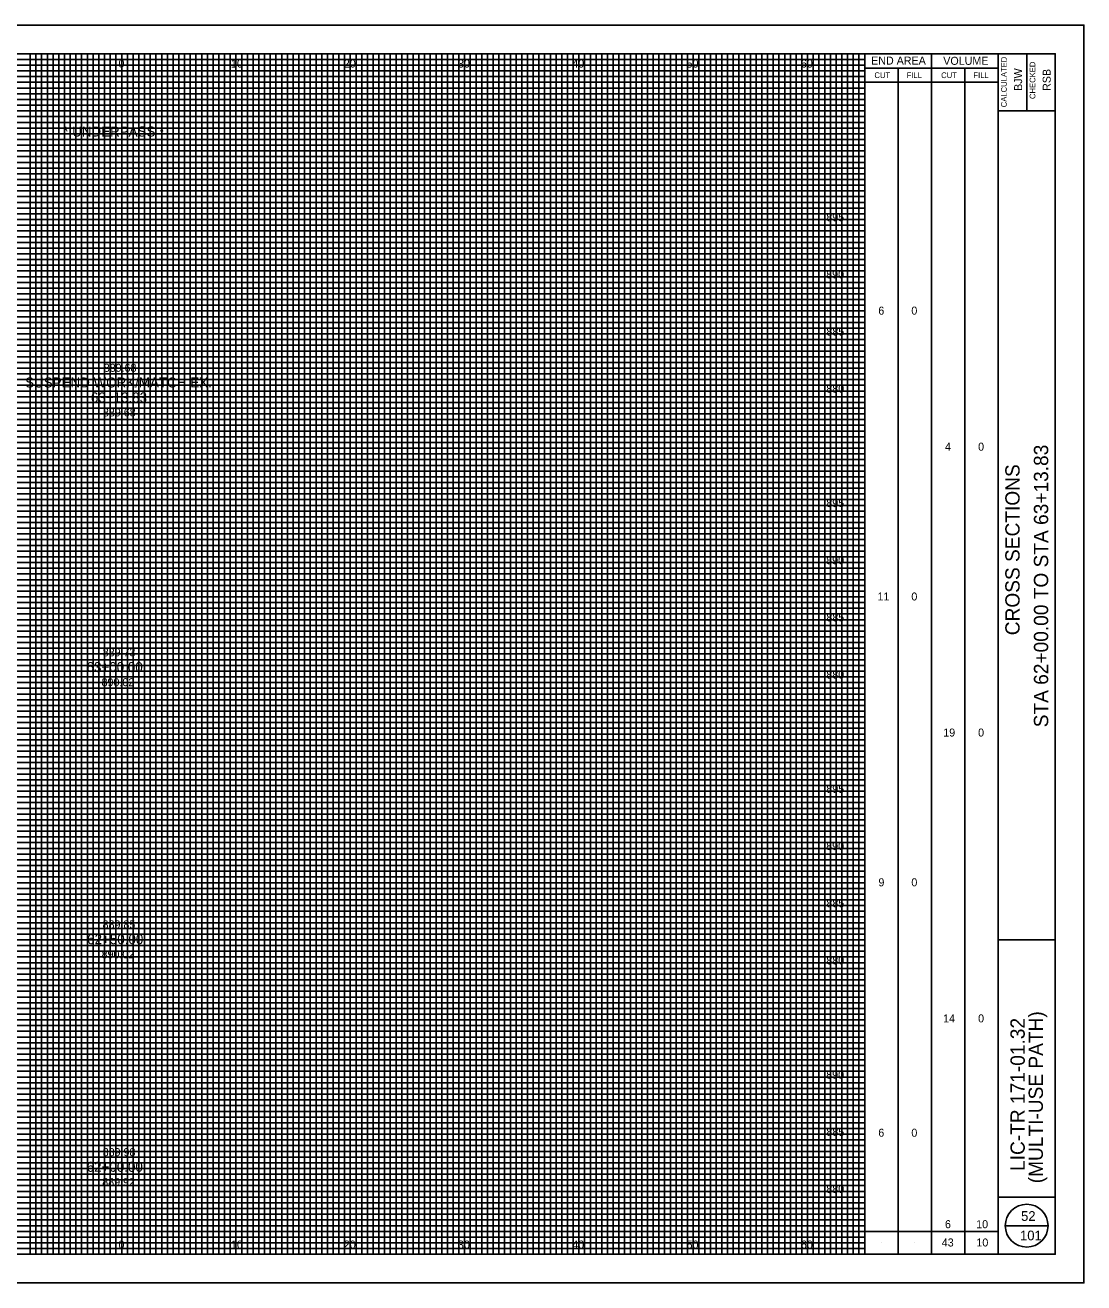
# Model space of a CAD drawing. Extents: x -10 to 160, y -2 to 222.
# Drawn here: x 67.4 to 160, y 112.5 to 222.5 of the extents above; entities that cross this region are included whole.
import ezdxf

# ---------------------------------------------------------------- set-up
doc = ezdxf.new("R2010")
doc.units = 0
for name, color, linetype in [('GK_Cells', 7, 'Continuous'), ('GK_Patterns', 7, 'Continuous'), ('SH_Cut_Line', 7, 'Continuous'), ('TX_P_10', 7, 'Continuous'), ('TX_X_10', 7, 'Continuous'), ('XS_P_Pavt_Surface', 7, 'Continuous'), ('XS_P_Text_Info', 7, 'Continuous'), ('XS_X_Ground_Line', 7, 'Continuous')]:
    doc.layers.add(name, color=color, linetype=linetype)

msp = doc.modelspace()

# ---------------------------------------------------------------- linework, layer by layer
at = {"layer": 'GK_Cells'}
msp.add_lwpolyline([(-10, 112.5), (160, 112.5), (160, 222.5), (-10, 222.5)], close=True, dxfattribs=at)
at = {"layer": 'TX_P_10'}
for p, q in [((140.83, 115), (140.83, 220)), ((146.67, 115), (146.67, 220)), ((140.83, 218.75), (152.5, 218.75)), ((143.75, 115), (143.75, 218.75)), ((149.58, 115), (149.58, 218.75)), ((140.83, 217.5), (152.5, 217.5)), ((140.83, 117), (152.5, 117)), ((153.12, 117.5), (156.88, 117.5)), ((142.29, 116), (142.29, 116)), ((145.21, 116), (145.21, 116)), ((148.12, 116), (148.12, 116)), ((151.04, 116), (151.04, 116))]:
    msp.add_line(p, q, dxfattribs=at)
msp.add_circle((155, 117.5), 1.87, dxfattribs=at)
at = {"layer": 'TX_X_10'}
for p, q in [((70.83, 115), (70.83, 220)), ((75.83, 115), (75.83, 220)), ((80.83, 115), (80.83, 220)), ((85.83, 115), (85.83, 220)), ((90.83, 115), (90.83, 220)), ((95.83, 115), (95.83, 220)), ((100.83, 115), (100.83, 220)), ((105.83, 115), (105.83, 220)), ((110.83, 115), (110.83, 220)), ((115.83, 115), (115.83, 220)), ((120.83, 115), (120.83, 220)), ((125.83, 115), (125.83, 220)), ((130.83, 115), (130.83, 220)), ((135.83, 115), (135.83, 220)), ((5.83, 215), (140.83, 215)), ((5.83, 210), (140.83, 210)), ((5.83, 205), (140.83, 205)), ((5.83, 200), (140.83, 200)), ((5.83, 195), (140.83, 195)), ((5.83, 190), (140.83, 190)), ((5.83, 185), (140.83, 185)), ((5.83, 180), (140.83, 180)), ((5.83, 175), (140.83, 175)), ((5.83, 170), (140.83, 170)), ((5.83, 165), (140.83, 165)), ((5.83, 160), (140.83, 160)), ((5.83, 155), (140.83, 155)), ((5.83, 150), (140.83, 150)), ((5.83, 145), (140.83, 145)), ((5.83, 140), (140.83, 140)), ((5.83, 135), (140.83, 135)), ((5.83, 130), (140.83, 130)), ((5.83, 125), (140.83, 125)), ((5.83, 120), (140.83, 120))]:
    msp.add_line(p, q, dxfattribs=at)
at = {"layer": 'XS_P_Pavt_Surface'}
for p, q in [((152.5, 115), (152.5, 220)), ((155, 220), (155, 215)), ((152.5, 215), (157.5, 215)), ((152.5, 142.5), (157.5, 142.5)), ((152.5, 120), (157.5, 120))]:
    msp.add_line(p, q, dxfattribs=at)
msp.add_lwpolyline([(0, 220), (157.5, 220), (157.5, 115), (0, 115)], close=True, dxfattribs=at)
at = {"layer": 'XS_X_Ground_Line'}
for p, q in [((5.83, 219.5), (140.83, 219.5)), ((5.83, 219), (140.83, 219)), ((67.83, 115), (67.83, 220)), ((68.33, 115), (68.33, 220)), ((68.83, 115), (68.83, 220)), ((69.33, 115), (69.33, 220)), ((69.83, 115), (69.83, 220)), ((70.33, 115), (70.33, 220)), ((71.33, 115), (71.33, 220)), ((71.83, 115), (71.83, 220)), ((72.33, 115), (72.33, 220)), ((72.83, 115), (72.83, 220)), ((73.33, 115), (73.33, 220)), ((73.83, 115), (73.83, 220)), ((74.33, 115), (74.33, 220)), ((74.83, 115), (74.83, 220)), ((75.33, 115), (75.33, 220)), ((76.33, 115), (76.33, 220)), ((76.83, 115), (76.83, 220)), ((77.33, 115), (77.33, 220)), ((77.83, 115), (77.83, 220)), ((78.33, 115), (78.33, 220)), ((78.83, 115), (78.83, 220)), ((79.33, 115), (79.33, 220)), ((79.83, 115), (79.83, 220)), ((80.33, 115), (80.33, 220)), ((81.33, 115), (81.33, 220)), ((81.83, 115), (81.83, 220)), ((82.33, 115), (82.33, 220)), ((82.83, 115), (82.83, 220)), ((83.33, 115), (83.33, 220)), ((83.83, 115), (83.83, 220)), ((84.33, 115), (84.33, 220)), ((84.83, 115), (84.83, 220)), ((85.33, 115), (85.33, 220)), ((86.33, 115), (86.33, 220)), ((86.83, 115), (86.83, 220)), ((87.33, 115), (87.33, 220)), ((87.83, 115), (87.83, 220)), ((88.33, 115), (88.33, 220)), ((88.83, 115), (88.83, 220)), ((89.33, 115), (89.33, 220)), ((89.83, 115), (89.83, 220)), ((90.33, 115), (90.33, 220)), ((91.33, 115), (91.33, 220)), ((91.83, 115), (91.83, 220)), ((92.33, 115), (92.33, 220)), ((92.83, 115), (92.83, 220)), ((93.33, 115), (93.33, 220)), ((93.83, 115), (93.83, 220)), ((94.33, 115), (94.33, 220)), ((94.83, 115), (94.83, 220)), ((95.33, 115), (95.33, 220)), ((96.33, 115), (96.33, 220)), ((96.83, 115), (96.83, 220)), ((97.33, 115), (97.33, 220)), ((97.83, 115), (97.83, 220)), ((98.33, 115), (98.33, 220)), ((98.83, 115), (98.83, 220)), ((99.33, 115), (99.33, 220)), ((99.83, 115), (99.83, 220)), ((100.33, 115), (100.33, 220)), ((101.33, 115), (101.33, 220)), ((101.83, 115), (101.83, 220)), ((102.33, 115), (102.33, 220)), ((102.83, 115), (102.83, 220)), ((103.33, 115), (103.33, 220)), ((103.83, 115), (103.83, 220)), ((104.33, 115), (104.33, 220)), ((104.83, 115), (104.83, 220)), ((105.33, 115), (105.33, 220)), ((106.33, 115), (106.33, 220)), ((106.83, 115), (106.83, 220)), ((107.33, 115), (107.33, 220)), ((107.83, 115), (107.83, 220)), ((108.33, 115), (108.33, 220)), ((108.83, 115), (108.83, 220)), ((109.33, 115), (109.33, 220)), ((109.83, 115), (109.83, 220)), ((110.33, 115), (110.33, 220)), ((111.33, 115), (111.33, 220)), ((111.83, 115), (111.83, 220)), ((112.33, 115), (112.33, 220)), ((112.83, 115), (112.83, 220)), ((113.33, 115), (113.33, 220)), ((113.83, 115), (113.83, 220)), ((114.33, 115), (114.33, 220)), ((114.83, 115), (114.83, 220)), ((115.33, 115), (115.33, 220)), ((116.33, 115), (116.33, 220)), ((116.83, 115), (116.83, 220)), ((117.33, 115), (117.33, 220)), ((117.83, 115), (117.83, 220)), ((118.33, 115), (118.33, 220)), ((118.83, 115), (118.83, 220)), ((119.33, 115), (119.33, 220)), ((119.83, 115), (119.83, 220)), ((120.33, 115), (120.33, 220)), ((121.33, 115), (121.33, 220)), ((121.83, 115), (121.83, 220)), ((122.33, 115), (122.33, 220)), ((122.83, 115), (122.83, 220)), ((123.33, 115), (123.33, 220)), ((123.83, 115), (123.83, 220)), ((124.33, 115), (124.33, 220)), ((124.83, 115), (124.83, 220)), ((125.33, 115), (125.33, 220)), ((126.33, 115), (126.33, 220)), ((126.83, 115), (126.83, 220)), ((127.33, 115), (127.33, 220)), ((127.83, 115), (127.83, 220)), ((128.33, 115), (128.33, 220)), ((128.83, 115), (128.83, 220)), ((129.33, 115), (129.33, 220)), ((129.83, 115), (129.83, 220)), ((130.33, 115), (130.33, 220)), ((131.33, 115), (131.33, 220)), ((131.83, 115), (131.83, 220)), ((132.33, 115), (132.33, 220)), ((132.83, 115), (132.83, 220)), ((133.33, 115), (133.33, 220)), ((133.83, 115), (133.83, 220)), ((134.33, 115), (134.33, 220)), ((134.83, 115), (134.83, 220)), ((135.33, 115), (135.33, 220)), ((136.33, 115), (136.33, 220)), ((136.83, 115), (136.83, 220)), ((137.33, 115), (137.33, 220)), ((137.83, 115), (137.83, 220)), ((138.33, 115), (138.33, 220)), ((138.83, 115), (138.83, 220)), ((139.33, 115), (139.33, 220)), ((139.83, 115), (139.83, 220)), ((140.33, 115), (140.33, 220)), ((5.83, 218.5), (140.83, 218.5)), ((5.83, 218), (140.83, 218)), ((5.83, 217.5), (140.83, 217.5)), ((5.83, 217), (140.83, 217)), ((5.83, 216.5), (140.83, 216.5)), ((5.83, 216), (140.83, 216)), ((5.83, 215.5), (140.83, 215.5)), ((5.83, 214.5), (140.83, 214.5)), ((5.83, 214), (140.83, 214)), ((5.83, 213.5), (140.83, 213.5)), ((5.83, 213), (140.83, 213)), ((5.83, 212.5), (140.83, 212.5)), ((5.83, 212), (140.83, 212)), ((5.83, 211.5), (140.83, 211.5)), ((5.83, 211), (140.83, 211)), ((5.83, 210.5), (140.83, 210.5)), ((5.83, 209.5), (140.83, 209.5)), ((5.83, 209), (140.83, 209)), ((5.83, 208.5), (140.83, 208.5)), ((5.83, 208), (140.83, 208)), ((5.83, 207.5), (140.83, 207.5)), ((5.83, 207), (140.83, 207)), ((5.83, 206.5), (140.83, 206.5)), ((5.83, 206), (140.83, 206)), ((5.83, 205.5), (140.83, 205.5)), ((5.83, 204.5), (140.83, 204.5)), ((5.83, 204), (140.83, 204)), ((5.83, 203.5), (140.83, 203.5)), ((5.83, 203), (140.83, 203)), ((5.83, 202.5), (140.83, 202.5)), ((5.83, 202), (140.83, 202)), ((5.83, 201.5), (140.83, 201.5)), ((5.83, 201), (140.83, 201)), ((5.83, 200.5), (140.83, 200.5)), ((5.83, 199.5), (140.83, 199.5)), ((5.83, 199), (140.83, 199)), ((5.83, 198.5), (140.83, 198.5)), ((5.83, 198), (140.83, 198)), ((5.83, 197.5), (140.83, 197.5)), ((5.83, 197), (140.83, 197)), ((5.83, 196.5), (140.83, 196.5)), ((5.83, 196), (140.83, 196)), ((5.83, 195.5), (140.83, 195.5)), ((5.83, 194.5), (140.83, 194.5)), ((5.83, 194), (140.83, 194)), ((5.83, 193.5), (140.83, 193.5)), ((5.83, 193), (140.83, 193)), ((5.83, 192.5), (140.83, 192.5)), ((5.83, 192), (140.83, 192)), ((5.83, 191.5), (140.83, 191.5)), ((5.83, 191), (140.83, 191)), ((5.83, 190.5), (140.83, 190.5)), ((5.83, 189.5), (140.83, 189.5)), ((5.83, 189), (140.83, 189)), ((5.83, 188.5), (140.83, 188.5)), ((5.83, 188), (140.83, 188)), ((5.83, 187.5), (140.83, 187.5)), ((5.83, 187), (140.83, 187)), ((5.83, 186.5), (140.83, 186.5)), ((5.83, 186), (140.83, 186)), ((5.83, 185.5), (140.83, 185.5)), ((5.83, 184.5), (140.83, 184.5)), ((5.83, 184), (140.83, 184)), ((5.83, 183.5), (140.83, 183.5)), ((5.83, 183), (140.83, 183)), ((5.83, 182.5), (140.83, 182.5)), ((5.83, 182), (140.83, 182)), ((5.83, 181.5), (140.83, 181.5)), ((5.83, 181), (140.83, 181)), ((5.83, 180.5), (140.83, 180.5)), ((5.83, 179.5), (140.83, 179.5)), ((5.83, 179), (140.83, 179)), ((5.83, 178.5), (140.83, 178.5)), ((5.83, 178), (140.83, 178)), ((5.83, 177.5), (140.83, 177.5)), ((5.83, 177), (140.83, 177)), ((5.83, 176.5), (140.83, 176.5)), ((5.83, 176), (140.83, 176)), ((5.83, 175.5), (140.83, 175.5)), ((5.83, 174.5), (140.83, 174.5)), ((5.83, 174), (140.83, 174)), ((5.83, 173.5), (140.83, 173.5)), ((5.83, 173), (140.83, 173)), ((5.83, 172.5), (140.83, 172.5)), ((5.83, 172), (140.83, 172)), ((5.83, 171.5), (140.83, 171.5)), ((5.83, 171), (140.83, 171)), ((5.83, 170.5), (140.83, 170.5)), ((5.83, 169.5), (140.83, 169.5)), ((5.83, 169), (140.83, 169)), ((5.83, 168.5), (140.83, 168.5)), ((5.83, 168), (140.83, 168)), ((5.83, 167.5), (140.83, 167.5)), ((5.83, 167), (140.83, 167)), ((5.83, 166.5), (140.83, 166.5)), ((5.83, 166), (140.83, 166)), ((5.83, 165.5), (140.83, 165.5)), ((5.83, 164.5), (140.83, 164.5)), ((5.83, 164), (140.83, 164)), ((5.83, 163.5), (140.83, 163.5)), ((5.83, 163), (140.83, 163)), ((5.83, 162.5), (140.83, 162.5)), ((5.83, 162), (140.83, 162)), ((5.83, 161.5), (140.83, 161.5)), ((5.83, 161), (140.83, 161)), ((5.83, 160.5), (140.83, 160.5)), ((5.83, 159.5), (140.83, 159.5)), ((5.83, 159), (140.83, 159)), ((5.83, 158.5), (140.83, 158.5)), ((5.83, 158), (140.83, 158)), ((5.83, 157.5), (140.83, 157.5)), ((5.83, 157), (140.83, 157)), ((5.83, 156.5), (140.83, 156.5)), ((5.83, 156), (140.83, 156)), ((5.83, 155.5), (140.83, 155.5)), ((5.83, 154.5), (140.83, 154.5)), ((5.83, 154), (140.83, 154)), ((5.83, 153.5), (140.83, 153.5)), ((5.83, 153), (140.83, 153)), ((5.83, 152.5), (140.83, 152.5)), ((5.83, 152), (140.83, 152)), ((5.83, 151.5), (140.83, 151.5)), ((5.83, 151), (140.83, 151)), ((5.83, 150.5), (140.83, 150.5)), ((5.83, 149.5), (140.83, 149.5)), ((5.83, 149), (140.83, 149)), ((5.83, 148.5), (140.83, 148.5)), ((5.83, 148), (140.83, 148)), ((5.83, 147.5), (140.83, 147.5)), ((5.83, 147), (140.83, 147)), ((5.83, 146.5), (140.83, 146.5)), ((5.83, 146), (140.83, 146)), ((5.83, 145.5), (140.83, 145.5)), ((5.83, 144.5), (140.83, 144.5)), ((5.83, 144), (140.83, 144)), ((5.83, 143.5), (140.83, 143.5)), ((5.83, 143), (140.83, 143)), ((5.83, 142.5), (140.83, 142.5)), ((5.83, 142), (140.83, 142)), ((5.83, 141.5), (140.83, 141.5)), ((5.83, 141), (140.83, 141)), ((5.83, 140.5), (140.83, 140.5)), ((5.83, 139.5), (140.83, 139.5)), ((5.83, 139), (140.83, 139)), ((5.83, 138.5), (140.83, 138.5)), ((5.83, 138), (140.83, 138)), ((5.83, 137.5), (140.83, 137.5)), ((5.83, 137), (140.83, 137)), ((5.83, 136.5), (140.83, 136.5)), ((5.83, 136), (140.83, 136)), ((5.83, 135.5), (140.83, 135.5)), ((5.83, 134.5), (140.83, 134.5)), ((5.83, 134), (140.83, 134)), ((5.83, 133.5), (140.83, 133.5)), ((5.83, 133), (140.83, 133)), ((5.83, 132.5), (140.83, 132.5)), ((5.83, 132), (140.83, 132)), ((5.83, 131.5), (140.83, 131.5)), ((5.83, 131), (140.83, 131)), ((5.83, 130.5), (140.83, 130.5)), ((5.83, 129.5), (140.83, 129.5)), ((5.83, 129), (140.83, 129)), ((5.83, 128.5), (140.83, 128.5)), ((5.83, 128), (140.83, 128)), ((5.83, 127.5), (140.83, 127.5)), ((5.83, 127), (140.83, 127)), ((5.83, 126.5), (140.83, 126.5)), ((5.83, 126), (140.83, 126)), ((5.83, 125.5), (140.83, 125.5)), ((5.83, 124.5), (140.83, 124.5)), ((5.83, 124), (140.83, 124)), ((5.83, 123.5), (140.83, 123.5)), ((5.83, 123), (140.83, 123)), ((5.83, 122.5), (140.83, 122.5)), ((5.83, 122), (140.83, 122)), ((5.83, 121.5), (140.83, 121.5)), ((5.83, 121), (140.83, 121)), ((5.83, 120.5), (140.83, 120.5)), ((5.83, 119.5), (140.83, 119.5)), ((5.83, 119), (140.83, 119)), ((5.83, 118.5), (140.83, 118.5)), ((5.83, 118), (140.83, 118)), ((5.83, 117.5), (140.83, 117.5)), ((5.83, 117), (140.83, 117)), ((5.83, 116.5), (140.83, 116.5)), ((5.83, 116), (140.83, 116)), ((5.83, 115.5), (140.83, 115.5))]:
    msp.add_line(p, q, dxfattribs=at)

# ---------------------------------------------------------------- texts
at = {"layer": 'GK_Patterns'}
for s, height, p in [('0', 0.7, (75.55, 218.79)), ('0', 0.7, (75.55, 218.79)), ('10', 0.7, (85.39, 218.79)), ('20', 0.7, (95.26, 218.79)), ('30', 0.7, (105.25, 218.79)), ('40', 0.7, (115.25, 218.79)), ('50', 0.7, (125.25, 218.79)), ('60', 0.7, (135.25, 218.79)), ('* UNDERPASS *', 0.875, (70.72, 212.76)), ('895', 0.7, (137.47, 205.35)), ('890', 0.7, (137.46, 200.35)), ('6', 0.7, (142.02, 197.18)), ('0', 0.7, (144.91, 197.18)), ('885', 0.7, (137.48, 195.35)), ('SUSPEND WORK/MATCH EX.', 0.875, (67.39, 190.81)), ('63+13.83', 0.875, (73.14, 189.5)), ('880', 0.7, (137.47, 190.35)), ('4', 0.7, (147.85, 185.28)), ('0', 0.7, (150.75, 185.28)), ('895', 0.7, (137.47, 180.35)), ('890', 0.7, (137.46, 175.35)), ('11', 0.7, (141.95, 172.18)), ('0', 0.7, (144.91, 172.18)), ('885', 0.7, (137.48, 170.35)), ('63+00.00', 0.875, (72.76, 165.92)), ('880', 0.7, (137.47, 165.35)), ('19', 0.7, (147.7, 160.28)), ('0', 0.7, (150.75, 160.28)), ('895', 0.7, (137.47, 155.35)), ('890', 0.7, (137.46, 150.35)), ('9', 0.7, (142.03, 147.18)), ('0', 0.7, (144.91, 147.18)), ('885', 0.7, (137.48, 145.35)), ('62+50.00', 0.875, (72.81, 142.12)), ('880', 0.7, (137.47, 140.35)), ('14', 0.7, (147.69, 135.28)), ('0', 0.7, (150.75, 135.28)), ('890', 0.7, (137.46, 130.35)), ('885', 0.7, (137.48, 125.35)), ('6', 0.7, (142.02, 125.28)), ('0', 0.7, (144.91, 125.28)), ('62+00.00', 0.875, (72.77, 122.21)), ('880', 0.7, (137.47, 120.35)), ('6', 0.7, (147.85, 117.28)), ('10', 0.7, (150.58, 117.28)), ('0', 0.7, (75.55, 115.5)), ('0', 0.7, (75.55, 115.5)), ('10', 0.7, (85.39, 115.5)), ('20', 0.7, (95.26, 115.5)), ('30', 0.7, (105.25, 115.5)), ('40', 0.7, (115.25, 115.5)), ('50', 0.7, (125.25, 115.5)), ('60', 0.7, (135.25, 115.5)), ('43', 0.7, (147.57, 115.68)), ('10', 0.7, (150.6, 115.68))]:
    msp.add_text(s, height=height, dxfattribs=at).set_placement(p)
at = {"layer": 'SH_Cut_Line'}
for s, p in [('889.68', (74.19, 188.28)), ('890.02', (74.07, 164.68)), ('890.02', (74.07, 140.88)), ('889.92', (74.13, 120.97))]:
    msp.add_text(s, height=0.7, dxfattribs=at).set_placement(p)
at = {"layer": 'TX_P_10'}
for s, height, p in [('END AREA', 0.7, (141.39, 219.05)), ('VOLUME', 0.7, (147.7, 219.03)), ('CUT', 0.5, (141.68, 217.87)), ('FILL', 0.5, (144.5, 217.87)), ('CUT', 0.5, (147.52, 217.87)), ('FILL', 0.5, (150.34, 217.87)), ('52', 0.85, (154.51, 117.92)), ('101', 0.85, (154.42, 116.22))]:
    msp.add_text(s, height=height, dxfattribs=at).set_placement(p)
for s, height, p in [('CALCULATED', 0.5, (153.26, 215.32)), ('CHECKED', 0.5, (155.76, 216.04)), ('BJW', 0.7, (154.6, 216.75)), ('RSB', 0.7, (157.1, 216.75)), ('STA 62+00.00 TO STA 63+13.83', 1.25, (156.88, 161.09)), ('CROSS SECTIONS', 1.25, (154.38, 169.14)), ('LIC-TR 171-01.32', 1.25, (154.83, 122.29)), ('(MULTI-USE PATH)', 1.25, (156.42, 121.21))]:
    msp.add_text(s, height=height, rotation=90, dxfattribs=at).set_placement(p)
at = {"layer": 'XS_P_Text_Info'}
for s, p in [('889.68', (74.26, 192.18)), ('889.73', (74.17, 167.3)), ('889.85', (74.16, 143.5)), ('889.98', (74.17, 123.58))]:
    msp.add_text(s, height=0.7, dxfattribs=at).set_placement(p)

doc.saveas('drawing.dxf')
